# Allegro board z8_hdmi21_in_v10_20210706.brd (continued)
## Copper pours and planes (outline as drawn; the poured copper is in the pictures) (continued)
(no net) on TOP: 22.86,124.9 23.75,124.9 24.13,125.29 24.13,126.05 24.26,126.17 24.77,126.17 24.89,126.05 24.89,123.51 24.77,123.38 22.86,123.38 22.73,123.51 22.73,124.78
(no net) on TOP: 124.21,142.81 124.21,141.16 124.08,141.03 120.78,141.03 120.65,141.16 120.65,142.81 120.78,142.94 124.08,142.94
(no net) on TOP: 1.02,99.12 1.4,99.5 10.92,99.5 11.18,99.25 11.18,79.69 10.92,79.44 1.4,79.44 1.02,79.82
(no net) on TOP: 71.37,22.8 71.37,21.53 72.9,20 75.82,20 75.95,20.13 75.95,22.54 75.82,22.67 72.52,22.67 72.26,22.92 71.5,22.92
(no net) on TOP: 129.92,139.89 129.92,138.49 129.79,138.37 110.36,138.37 108.33,140.4 108.33,142.81 108.46,142.94 110.11,142.94 110.36,143.19 112.01,143.19 112.14,143.07 112.14,140.78 112.9,140.02 129.79,140.02
(no net) on TOP: 21.46,103.06 17.78,103.06 17.65,102.93 17.65,100.65 17.78,100.52 21.46,100.52 21.59,100.65 21.59,102.93
(no net) on TOP: 181.99,125.29 181.99,127.7 182.12,127.83 185.29,127.83 185.42,127.7 185.42,126.56 185.29,126.43 183.52,126.43 183.13,126.05 183.13,125.29 183.01,125.16 182.12,125.16
(no net) on TOP: 21.59,123.51 21.46,123.38 15.37,123.38 15.24,123.51 15.24,126.68 15.37,126.81 21.46,126.81 21.59,126.68
(no net) on TOP: 14.73,39.31 14.73,40.2 14.61,40.32 14.1,40.32 13.97,40.2 13.97,39.81 12.06,37.91 11.81,37.91 11.68,37.78 11.68,37.27 11.81,37.15 12.57,37.15
(no net) on TOP: 65.79,22.8 65.79,21.53 64.26,20 61.34,20 61.21,20.13 61.21,22.54 61.34,22.67 64.64,22.67 64.9,22.92 65.66,22.92
(no net) on TOP: 14.73,123.13 14.73,124.02 14.61,124.14 14.1,124.14 13.97,124.02 13.97,123.63 12.06,121.73 11.81,121.73 11.68,121.6 11.68,121.09 11.81,120.97 12.57,120.97
(no net) on TOP: 1.02,43.24 1.4,43.62 10.92,43.62 11.18,43.37 11.18,23.81 10.92,23.56 1.4,23.56 1.02,23.94
(no net) on TOP: 24.13,45.15 24,45.28 24,45.91 23.88,46.04 22.61,46.04 22.1,46.55 22.1,47.05 22.23,47.18 24.77,47.18 24.89,47.05 24.89,45.28 24.77,45.15
(no net) on TOP: 22.86,69.02 23.75,69.02 24.13,69.41 24.13,70.17 24.26,70.29 24.77,70.29 24.89,70.17 24.89,67.63 24.77,67.5 22.86,67.5 22.73,67.63 22.73,68.9
(no net) on TOP: 183.77,116.01 182.12,116.01 181.99,116.14 181.99,119.57 182.12,119.7 183.77,119.7 183.9,119.57 183.9,116.14
(no net) on TOP: 14.73,95.19 14.73,96.08 14.61,96.2 14.1,96.2 13.97,96.08 13.97,95.69 12.06,93.79 11.81,93.79 11.68,93.66 11.68,93.15 11.81,93.03 12.57,93.03
(no net) on TOP: 21.46,47.18 17.78,47.18 17.65,47.05 17.65,44.77 17.78,44.64 21.46,44.64 21.59,44.77 21.59,47.05
(no net) on TOP: 14.73,67.25 14.73,68.14 14.61,68.26 14.1,68.26 13.97,68.14 13.97,67.75 12.06,65.85 11.81,65.85 11.68,65.72 11.68,65.21 11.81,65.09 12.57,65.09
(no net) on TOP: 111.38,22.8 111.38,21.53 109.86,20 106.93,20 106.81,20.13 106.81,22.54 106.93,22.67 110.24,22.67 110.49,22.92 111.25,22.92
(no net) on TOP: 204.47,130.75 205.74,130.75 207.26,129.22 207.26,126.3 207.14,126.17 204.72,126.17 204.6,126.3 204.6,129.6 204.34,129.86 204.34,130.62
(no net) on TOP: 119,144.34 118.87,144.46 118.87,145.1 119,145.22 126.36,145.22 127.89,143.7 139.7,143.7 139.83,143.57 139.83,141.16 139.7,141.03 124.84,141.03 124.71,141.16 124.71,143.07 124.33,143.45 120.27,143.45 120.02,143.7 120.02,144.21 119.89,144.34
(no net) on TOP: 184.66,68.64 184.66,66.23 184.53,66.1 181.36,66.1 181.23,66.23 181.23,67.37 181.36,67.5 183.13,67.5 183.52,67.88 183.52,68.64 183.64,68.77 184.53,68.77
(no net) on TOP: 182.88,77.79 184.53,77.79 184.66,77.66 184.66,74.36 184.53,74.23 182.88,74.23 182.75,74.36 182.75,77.66
(no net) on TOP: 1.02,71.18 1.4,71.56 10.92,71.56 11.18,71.31 11.18,51.75 10.92,51.5 1.4,51.5 1.02,51.88
(no net) on TOP: 116.97,22.8 116.97,21.53 118.49,20 121.41,20 121.54,20.13 121.54,22.54 121.41,22.67 118.11,22.67 117.86,22.92 117.09,22.92
(no net) on TOP: 21.59,67.63 21.46,67.5 15.37,67.5 15.24,67.63 15.24,70.8 15.37,70.93 21.46,70.93 21.59,70.8
(no net) on TOP: 1.02,127.06 1.4,127.44 10.92,127.44 11.18,127.19 11.18,107.63 10.92,107.38 1.4,107.38 1.02,107.76
(no net) on TOP: 24.13,73.09 24,73.22 24,73.85 23.88,73.98 22.61,73.98 22.1,74.49 22.1,74.99 22.23,75.12 24.77,75.12 24.89,74.99 24.89,73.22 24.77,73.09
(no net) on TOP: 24.13,128.97 24,129.1 24,129.73 23.88,129.86 22.61,129.86 22.1,130.37 22.1,130.87 22.23,131 24.77,131 24.89,130.87 24.89,129.1 24.77,128.97
(no net) on TOP: 115.06,141.03 112.65,141.03 112.52,141.16 112.52,144.34 112.65,144.46 113.79,144.46 113.92,144.34 113.92,142.56 114.3,142.18 115.06,142.18 115.19,142.05 115.19,141.16
(no net) on TOP: 180.47,70.17 181.36,70.17 181.36,69.15 180.72,68.52 180.72,66.1 181.1,65.72 181.86,65.72 181.99,65.6 181.99,63.94 181.74,63.69 181.74,62.04 181.61,61.91 179.83,61.91 179.71,62.04 179.71,69.41
(no net) on BOTTOM: 40.51,55.31 40.51,53.78 40.39,53.66 38.99,53.66 38.86,53.78 38.86,55.31 38.99,55.44 40.39,55.44
(no net) on BOTTOM: 127.89,33.97 127.89,30.8 127.76,30.67 106.17,30.67 106.05,30.8 106.05,33.97 106.17,34.1 127.76,34.1
(no net) on BOTTOM: 185.1,30.54 184.91,30.73 184.91,35.24 185.04,35.37 194.69,35.37 194.82,35.24 194.82,30.67 194.69,30.54
(no net) on BOTTOM: 86.49,34.1 102.74,34.1 102.87,33.97 102.87,30.8 102.74,30.67 86.49,30.67 86.36,30.8 86.36,33.97
(no net) on BOTTOM: 38.99,121.48 41.53,121.48 41.66,121.35 41.66,120.21 41.53,120.08 38.99,120.08 38.86,120.21 38.86,121.35
(no net) on BOTTOM: 40.51,27.37 40.51,25.84 40.39,25.72 38.99,25.72 38.86,25.84 38.86,27.37 38.99,27.5 40.39,27.5
(no net) on BOTTOM: 38.99,65.6 41.53,65.6 41.66,65.47 41.66,64.33 41.53,64.2 38.99,64.2 38.86,64.33 38.86,65.47
(no net) on BOTTOM: 36.2,36.26 36.2,35.12 36.32,34.99 39.12,34.99 39.24,35.12 39.24,35.62 39.12,35.75 38.48,35.75 38.1,36.13 38.1,38.42 37.97,38.54 35.81,38.54 35.69,38.42 35.69,36.77
(no net) on BOTTOM: 40.51,83.25 40.51,81.72 40.39,81.6 38.99,81.6 38.86,81.72 38.86,83.25 38.99,83.38 40.39,83.38
(no net) on BOTTOM: 59.94,34.23 82.17,34.23 82.3,34.1 82.3,30.8 82.17,30.67 59.94,30.67 59.82,30.8 59.82,34.1
(no net) on BOTTOM: 36.2,92.14 36.2,91 36.32,90.87 39.12,90.87 39.24,91 39.24,91.5 39.12,91.63 38.48,91.63 38.1,92.01 38.1,94.3 37.97,94.42 35.81,94.42 35.69,94.3 35.69,92.65
(no net) on BOTTOM: 193.17,124.78 193.17,147.13 193.29,147.26 196.6,147.26 196.72,147.13 196.72,124.78 196.6,124.65 193.29,124.65
(no net) on BOTTOM: 36.2,120.08 36.2,118.94 36.32,118.81 39.12,118.81 39.24,118.94 39.24,119.44 39.12,119.57 38.48,119.57 38.1,119.95 38.1,122.11 37.97,122.24 35.81,122.24 35.69,122.11 35.69,120.59
(no net) on BOTTOM: 40.51,111.19 40.51,109.66 40.39,109.54 38.99,109.54 38.86,109.66 38.86,111.19 38.99,111.32 40.39,111.32
(no net) on BOTTOM: 36.2,64.2 36.2,63.06 36.32,62.93 39.12,62.93 39.24,63.06 39.24,63.56 39.12,63.69 38.48,63.69 38.1,64.07 38.1,66.36 37.97,66.48 35.81,66.48 35.69,66.36 35.69,64.71
(no net) on BOTTOM: 183.9,96.71 184.02,96.58 184.02,81.22 183.9,81.09 182.12,81.09 181.99,81.22 181.99,96.58 182.12,96.71
(no net) on BOTTOM: 34.67,112.08 37.97,112.08 38.1,111.95 38.1,110.55 37.97,110.43 34.67,110.43 34.54,110.55 34.54,111.95
(no net) on BOTTOM: 127,142.94 127.13,143.07 142.49,143.07 142.62,142.94 142.62,141.16 142.49,141.03 127.13,141.03 127,141.16
(no net) on BOTTOM: 34.67,84.14 37.97,84.14 38.1,84.01 38.1,82.61 37.97,82.49 34.67,82.49 34.54,82.61 34.54,84.01
(no net) on BOTTOM: 34.67,56.2 37.97,56.2 38.1,56.07 38.1,54.67 37.97,54.55 34.67,54.55 34.54,54.67 34.54,56.07
(no net) on BOTTOM: 34.67,28.26 37.97,28.26 38.1,28.13 38.1,26.73 37.97,26.61 34.67,26.61 34.54,26.73 34.54,28.13
(no net) on BOTTOM: 183.9,113.35 184.02,113.22 184.02,97.85 183.9,97.73 182.12,97.73 181.99,97.85 181.99,113.22 182.12,113.35
(no net) on BOTTOM: 38.99,37.66 41.53,37.66 41.66,37.53 41.66,36.64 41.4,36.39 38.99,36.39 38.86,36.51 38.86,37.53
(no net) on BOTTOM: 38.99,93.54 41.53,93.54 41.66,93.41 41.66,92.27 41.53,92.14 38.99,92.14 38.86,92.27 38.86,93.41
VREF_DDR3_A on TOP (solid shape): 116.59,145.22 116.59,144.34 115.56,144.34 114.94,144.97 112.52,144.97 112.14,144.59 112.14,143.83 112.01,143.7 110.36,143.7 110.11,143.95 108.46,143.95 108.33,144.08 108.33,145.86 108.46,145.99 115.82,145.99
VREF_DDR3_A on 03_SIG1: 130.17,86.8 129.41,86.8 129.29,86.93 129.29,95.82 114.81,110.3 114.81,126.17 110.87,130.11 110.87,130.49 111,130.62 112.65,130.62 115.82,127.44 115.82,112.2 131.44,96.58 131.44,88.07
VREF_DDR3_B on TOP (solid shape): 186.94,131.89 186.94,124.52 186.18,123.76 185.3,123.76 185.3,124.78 185.93,125.41 185.93,127.83 185.55,128.21 184.78,128.21 184.66,128.33 184.66,129.98 184.91,130.24 184.91,131.89 185.04,132.02 186.82,132.02
VREF_DDR3_B on 03_SIG1: 138.94,100.65 138.56,101.03 138.56,111.44 140.21,113.09 140.21,117.41 141.1,118.3 141.1,118.68 140.84,118.94 140.46,118.94 139.19,117.67 139.19,113.47 137.16,111.44 137.16,98.74 137.29,98.62 140.21,98.62 140.34,98.74 140.34,100.52 140.21,100.65
VREF_DDR3_C on TOP (solid shape): 181.35,69.15 180.72,68.52 180.72,66.1 181.1,65.72 181.86,65.72 181.99,65.6 181.99,63.94 181.74,63.69 181.74,62.04 181.61,61.91 179.83,61.91 179.71,62.04 179.71,69.41 180.47,70.17 181.35,70.17
VREF_DDR3_C on 03_SIG1: 144.15,97.6 144.91,96.84 164.35,96.84 164.98,97.47 172.85,97.47 172.97,97.35 172.97,96.2 172.85,96.08 165.53,96.08 164.9,95.44 141.48,95.44 141.35,95.57 141.35,97.47 141.48,97.6
VTT_DDR3_A on TOP (solid shape): 127.89,143.7 139.7,143.7 139.83,143.57 139.83,141.16 139.7,141.03 124.84,141.03 124.71,141.16 124.71,143.07 124.33,143.45 120.27,143.45 120.02,143.7 120.02,144.21 119.89,144.34 119.83,144.34 119.83,144.34 118.99,144.34 118.87,144.46 118.87,145.1 119,145.22 126.36,145.22
VTT_DDR3_A on BOTTOM (solid shape): 142.62,142.94 142.62,141.16 142.49,141.03 127.13,141.03 127,141.16 127,142.94 127.13,143.07 142.49,143.07
VTT_DDR3_B on TOP (solid shape): 186.18,121.35 186.18,113.98 184.66,112.46 184.66,100.65 184.53,100.52 182.12,100.52 181.99,100.65 181.99,115.38 182.12,115.51 184.02,115.51 184.4,115.89 184.4,120.08 184.66,120.33 185.17,120.33 185.29,120.46 185.29,120.52 185.3,120.52 185.3,121.35 185.42,121.48 186.06,121.48
VTT_DDR3_B on BOTTOM (solid shape): 184.02,113.22 184.02,97.85 183.9,97.73 182.12,97.73 181.99,97.85 181.99,113.22 182.12,113.35 183.9,113.35
VTT_DDR3_C on TOP (solid shape): 184.66,94.93 184.66,78.42 184.53,78.3 182.63,78.3 182.25,77.91 182.25,73.85 181.99,73.6 181.48,73.6 181.36,73.47 181.36,73.41 181.35,73.41 181.35,72.58 181.23,72.45 180.59,72.45 180.47,72.58 180.47,79.95 181.99,81.47 181.99,95.06 182.12,95.19 184.4,95.19
VTT_DDR3_C on BOTTOM (solid shape): 184.02,96.58 184.02,81.22 183.9,81.09 182.12,81.09 181.99,81.22 181.99,96.58 182.12,96.71 183.9,96.71
N22026409 on TOP: 88.01,38.54 87.88,38.42 86.36,38.42 86.23,38.54 86.23,41.72 85.98,41.97 83.82,41.97 83.69,42.1 83.69,42.99 83.82,43.12 87.76,43.12 88.01,42.86
N22030137 on TOP: 83.44,156.53 83.06,156.91 83.06,165.54 82.3,166.31 1.4,166.31 1.02,166.69 1.02,167.01 1.04,167.29 1.1,167.58 1.83,168.63 3.05,169.04 256.03,169.04 257.4,168.51 258.06,167.2 258.06,167.1 258.06,167.01 258.06,166.69 257.68,166.31 198.5,166.31 197.74,165.54 197.74,156.91 197.36,156.53 185.04,156.53 184.66,156.91 184.66,165.54 183.9,166.31 147.7,166.31 146.94,165.54 146.94,156.91 146.56,156.53 134.24,156.53 133.86,156.91 133.86,165.54 133.1,166.31 96.9,166.31 96.14,165.54 96.14,156.91 95.76,156.53
N22030137 on BOTTOM: 83.06,165.54 82.3,166.31 1.52,166.31 1.02,166.81 1.02,167 1.61,168.44 3.05,169.04 256.03,169.04 257.47,168.44 258.06,167 258.06,166.81 257.56,166.31 198.5,166.31 197.74,165.54 197.74,156.91 197.36,156.53 185.04,156.53 184.66,156.91 184.66,165.54 183.9,166.31 147.7,166.31 146.94,165.54 146.94,156.91 146.56,156.53 134.24,156.53 133.86,156.91 133.86,165.54 133.1,166.31 96.9,166.31 96.14,165.54 96.14,156.91 95.76,156.53 83.44,156.53 83.06,156.91
N22030722 on TOP: 114.68,22.42 114.55,22.29 113.79,22.29 113.67,22.42 113.67,25.34 113.16,25.84 111.63,25.84 111.51,25.97 111.51,29.27 111.63,29.4 116.71,29.4 116.84,29.27 116.84,25.97 116.71,25.84 115.19,25.84 114.68,25.34
N22031163 on TOP: 159.38,24.32 163.58,24.32 163.7,24.45 163.7,29.4 163.58,29.53 157.86,29.53 157.73,29.4 157.73,25.72 157.86,25.59 159,25.59 159.26,25.34 159.26,24.45
N22031700 on TOP: 3.05,1.02 1.78,1.46 1.07,2.6 1.03,2.79 1.02,2.98 1.02,3.37 1.4,3.75 82.3,3.75 83.06,4.51 83.06,13.14 83.44,13.53 95.76,13.53 96.14,13.14 96.14,4.51 96.9,3.75 133.1,3.75 133.86,4.51 133.86,13.14 134.24,13.53 146.56,13.53 146.94,13.14 146.94,4.51 147.7,3.75 183.9,3.75 184.66,4.51 184.66,13.14 185.04,13.53 197.36,13.53 197.74,13.14 197.74,4.51 198.5,3.75 257.68,3.75 258.06,3.37 258.06,3.05 258.06,2.95 258.06,2.86 257.4,1.55 256.03,1.02
N22031700 on BOTTOM: 3.05,1.02 1.61,1.61 1.02,3.05 1.02,3.24 1.52,3.75 82.3,3.75 83.06,4.51 83.06,13.14 83.44,13.53 95.63,13.53 96.01,13.14 96.01,4.51 96.77,3.75 133.1,3.75 133.86,4.51 133.86,13.14 134.24,13.53 146.56,13.53 146.94,13.14 146.94,4.51 147.7,3.75 183.9,3.75 184.66,4.51 184.66,13.14 185.04,13.53 197.36,13.53 197.74,13.14 197.74,4.51 198.5,3.75 257.56,3.75 258.06,3.24 258.06,3.05 257.47,1.61 256.03,1.02
N22318199 on TOP (solid shape): outline of 775 points within 1.02,107.38 11.18,127.44
N22319555 on TOP (solid shape): 14.73,124.02 14.73,123.13 12.57,120.97 11.81,120.97 11.68,121.09 11.68,121.6 11.8,121.72 11.89,121.72 11.9,121.73 12.06,121.73 13.97,123.63 13.97,124.02 14.1,124.14 14.61,124.14
N22336470 on TOP (solid shape): outline of 775 points within 1.02,79.44 11.18,99.5
N22337826 on TOP (solid shape): 14.73,96.08 14.73,95.19 12.57,93.03 11.81,93.03 11.68,93.15 11.68,93.66 11.8,93.78 11.89,93.78 11.9,93.79 12.06,93.79 13.97,95.69 13.97,96.08 14.1,96.2 14.61,96.2
N22341875 on TOP (solid shape): outline of 775 points within 1.02,51.5 11.18,71.56
N22343231 on TOP (solid shape): 14.73,68.14 14.73,67.25 12.57,65.09 11.81,65.09 11.68,65.21 11.68,65.72 11.8,65.84 11.89,65.84 11.9,65.85 12.06,65.85 13.97,67.75 13.97,68.14 14.1,68.26 14.61,68.26
N22347179 on TOP (solid shape): outline of 775 points within 1.02,23.56 11.18,43.62
N22348531 on TOP (solid shape): 14.73,40.2 14.73,39.31 12.57,37.15 11.81,37.15 11.68,37.27 11.68,37.78 11.8,37.9 11.89,37.9 11.9,37.91 12.06,37.91 13.97,39.81 13.97,40.2 14.1,40.32 14.61,40.32
N22376675 on TOP: 1.02,154.88 1.52,155.38 10.92,155.38 11.18,155.13 11.18,135.57 10.92,135.32 1.4,135.32 1.02,135.7
N22449837 on TOP: 181.48,25.21 181.48,22.42 181.36,22.29 180.59,22.29 180.47,22.42 180.47,25.21 179.96,25.72 178.44,25.72 178.31,25.84 178.31,29.27 178.44,29.4 183.52,29.4 183.64,29.27 183.64,25.84 183.52,25.72 181.99,25.72
N22451846 on TOP: 204.85,92.14 204.98,92.01 204.98,91.25 204.85,91.12 201.93,91.12 201.42,90.61 201.42,89.09 201.3,88.96 197.99,88.96 197.87,89.09 197.87,94.17 197.99,94.3 201.3,94.3 201.42,94.17 201.42,92.65 201.93,92.14
N22647877 on TOP: 69.09,22.42 68.96,22.29 68.2,22.29 68.07,22.42 68.07,25.34 67.56,25.84 66.04,25.84 65.91,25.97 65.91,29.27 66.04,29.4 71.12,29.4 71.25,29.27 71.25,25.97 71.12,25.84 69.6,25.84 69.09,25.34
N22766096 on TOP: 95.76,22.42 95.63,22.29 94.87,22.29 94.74,22.42 94.74,25.34 94.23,25.84 92.71,25.84 92.58,25.97 92.58,29.27 92.71,29.4 97.79,29.4 97.92,29.27 97.92,25.97 97.79,25.84 96.27,25.84 95.76,25.34
N22768241 on TOP: 204.85,134.05 204.98,133.92 204.98,133.16 204.85,133.03 201.93,133.03 201.42,132.52 201.42,131 201.3,130.87 197.99,130.87 197.87,131 197.87,136.08 197.99,136.21 201.3,136.21 201.42,136.08 201.42,134.56 201.93,134.05
N22769670 on TOP: 205.1,30.29 205.23,30.16 205.23,28.51 205.1,28.38 199.26,28.38 199.14,28.51 199.14,30.16 199.26,30.29

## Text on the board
Ref Des/Silkscreen Bottom: A | GND | 12V
User.Comments: CR_HDMI_3
Ref Des/Silkscreen Top: 8 | 13 | 18 | 5 | 1 | 12 | SDA | SCL | D5V | D1V2 | 1V8 | D1V0 | 3 | 2 | D0V9 | IO_1V8 | D3V3 | D1V8 | 1V5 | D3V0 | RST | RX | TX | CLK | GND | IO | NC | TCK | TDO | TMS | TDI | 12V | 23-0714-A0
User.45: FIGURE | SIZE | 8.0 | 10.0 | 24.0 | 32.0 | 36.0 | 80.0 | 156.0 | 122.0 | 66.93x35.43 | 106.2992x27.5591 | 106.3x35.43 | DRILL CHART: TOP to BOTTOM | ALL UNITS ARE IN MILS | TOLERANCE | +3.0/-3.0 | +2.0/-2.0 | PLATED | NON-PLATED | QTY | 1719 | 3709 | 60 | 48 | 67 | 4 | 6 | 10 | 1 | 2
